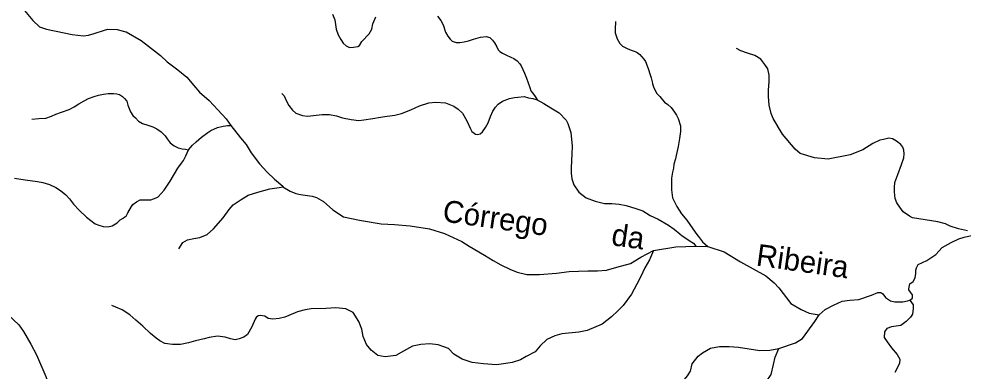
# Model space of a CAD drawing. Extents: x 436.3 to 500.4, y 8231 to 8286.4.
# Drawn here: x 484.1 to 492.75, y 8258.62 to 8261.84 of the extents above; entities that cross this region are included whole.
import ezdxf
from ezdxf.enums import TextEntityAlignment as Align

# ---------------------------------------------------------------- set-up
doc = ezdxf.new("R2010")
doc.units = 0
doc.header["$LTSCALE"] = 0.08
doc.linetypes.add('LONG_DASHED', pattern=[7.5, 6, -1.5])
doc.layers.add('61', color=7, linetype='Continuous')
doc.layers.add('9', color=7, linetype='LONG_DASHED', lineweight=25)

msp = doc.modelspace()

# ---------------------------------------------------------------- linework, layer by layer
at = {"layer": '9'}
msp.add_line((490.2994, 8259.7601), (490.4086, 8259.7547), dxfattribs=at)
for points in [[(484.1536, 8261.9144), (484.2296, 8261.8236), (484.2903, 8261.7668), (484.355, 8261.7442), (484.5186, 8261.7103), (484.5909, 8261.6953), (484.6936, 8261.684), (484.7394, 8261.6878), (484.7926, 8261.703), (484.8879, 8261.7334), (484.9184, 8261.7448), (485.0021, 8261.7411), (485.0707, 8261.7223), (485.0859, 8261.7185), (485.2229, 8261.6392), (485.2892, 8261.5876), (485.3995, 8261.5044), (485.4603, 8261.4439), (485.5592, 8261.3722), (485.6392, 8261.3041), (485.7039, 8261.2285), (485.757, 8261.168), (485.8446, 8261.0925), (485.9244, 8261.0054), (486.0006, 8260.9223), (486.0443, 8260.8634)], [(486.9745, 8261.8825), (486.9963, 8261.8298), (487.0085, 8261.743), (487.0241, 8261.6934), (487.0489, 8261.65), (487.0706, 8261.6159), (487.0987, 8261.5911), (487.1298, 8261.5756), (487.1671, 8261.5787), (487.2045, 8261.5848), (487.2202, 8261.5942), (487.2421, 8261.6314), (487.3076, 8261.7028), (487.3325, 8261.7431), (487.342, 8261.7927), (487.3702, 8261.8578)], [(487.9339, 8261.8623), (487.9642, 8261.823), (487.9858, 8261.7837), (488.0068, 8261.7158), (488.0296, 8261.679), (488.0499, 8261.6536), (488.0702, 8261.6346), (488.1057, 8261.6219), (488.1375, 8261.6219), (488.1782, 8261.6281), (488.2188, 8261.6383), (488.2646, 8261.6534), (488.3053, 8261.6647), (488.3294, 8261.6723), (488.3802, 8261.676), (488.4133, 8261.6684), (488.4386, 8261.6443), (488.4563, 8261.6202), (488.4766, 8261.5834), (488.4913, 8261.5547), (488.5053, 8261.5408), (488.5293, 8261.5243), (488.5674, 8261.5065), (488.6055, 8261.4886), (488.6334, 8261.4747), (488.6625, 8261.4544), (488.6892, 8261.4265), (488.7018, 8261.4087), (488.7309, 8261.3427), (488.7486, 8261.2946), (488.765, 8261.254), (488.7802, 8261.2109), (488.7903, 8261.1805), (488.8042, 8261.1602), (488.8296, 8261.1272), (488.8462, 8261.0973)], [(489.5625, 8261.8153), (489.5605, 8261.745), (489.5622, 8261.7112), (489.5685, 8261.6838), (489.5803, 8261.6564), (489.5903, 8261.6336), (489.6048, 8261.6117), (489.6294, 8261.5889), (489.6768, 8261.5633), (489.716, 8261.5495), (489.7424, 8261.5403), (489.7607, 8261.5302), (489.7852, 8261.5111), (489.8025, 8261.4936), (489.8246, 8261.4684), (489.8383, 8261.4474), (489.8528, 8261.4072), (489.8664, 8261.3735), (489.8791, 8261.3351), (489.8891, 8261.2995), (489.899, 8261.2622), (489.9037, 8261.2443), (489.9109, 8261.2178), (489.9227, 8261.1877), (489.9436, 8261.1549), (489.9682, 8261.1274), (489.9946, 8261.0973), (490.0138, 8261.0772), (490.0438, 8261.0552), (490.0739, 8261.0269), (490.1032, 8260.9861), (490.1222, 8260.9578), (490.1378, 8260.9277), (490.1592, 8260.8595), (490.1591, 8260.808), (490.1505, 8260.7437), (490.1375, 8260.6709), (490.1203, 8260.5896), (490.1135, 8260.5585), (490.098, 8260.5077), (490.0935, 8260.4722), (490.0868, 8260.4346), (490.0779, 8260.3814), (490.0756, 8260.3304), (490.0778, 8260.2728), (490.0866, 8260.2019), (490.1266, 8260.122), (490.1687, 8260.0532), (490.2156, 8259.9967), (490.2732, 8259.9167), (490.3087, 8259.8657), (490.3332, 8259.8347), (490.3597, 8259.7991), (490.4086, 8259.7547)], [(490.9571, 8261.3821), (490.9315, 8261.4193), (490.8938, 8261.4693), (490.8405, 8261.5017), (490.7715, 8261.5252), (490.7119, 8261.5458), (490.6711, 8261.5664)], [(492.7862, 8259.8999), (492.703, 8259.9175), (492.6259, 8259.9409), (492.5843, 8259.9644), (492.513, 8259.982), (492.2826, 8260.0192), (492.2541, 8260.0345), (492.1974, 8260.0729), (492.1665, 8260.1166), (492.1383, 8260.1551), (492.1228, 8260.1962), (492.1177, 8260.2553), (492.1177, 8260.2964), (492.1204, 8260.3401), (492.1489, 8260.4136), (492.1825, 8260.5062), (492.2033, 8260.5653), (492.206, 8260.6039), (492.2034, 8260.6374), (492.1932, 8260.6656), (492.1752, 8260.6887), (492.1366, 8260.7196), (492.098, 8260.7402), (492.067, 8260.7453), (492.0181, 8260.735), (491.9846, 8260.7273), (491.9196, 8260.6974), (491.8282, 8260.6389), (491.7108, 8260.5934), (491.5089, 8260.5546), (491.3852, 8260.5679), (491.2549, 8260.6071), (491.2095, 8260.6462), (491.0925, 8260.7831), (491.0083, 8260.9264), (490.9888, 8260.972), (490.9694, 8261.0501), (490.9631, 8261.1282), (490.9632, 8261.1868), (490.9699, 8261.2649), (490.97, 8261.3235), (490.9571, 8261.3821)], [(484.2208, 8260.9201), (484.2868, 8260.9269), (484.3483, 8260.9293), (484.403, 8260.9474), (484.4417, 8260.9656), (484.4918, 8260.9838), (484.5632, 8261.0088), (484.6088, 8261.0338), (484.6521, 8261.061), (484.7, 8261.0883), (484.741, 8261.1087), (484.7911, 8261.1268), (484.8322, 8261.1405), (484.8777, 8261.1496), (484.9187, 8261.1542), (484.9689, 8261.1543), (484.9985, 8261.152), (485.0236, 8261.1452), (485.0509, 8261.1271), (485.0691, 8261.1091), (485.0896, 8261.0842), (485.1009, 8261.048), (485.1123, 8261.0185), (485.1259, 8260.9868), (485.1464, 8260.9551), (485.1692, 8260.9326), (485.1988, 8260.9009), (485.2329, 8260.8805), (485.283, 8260.867), (485.3287, 8260.8512), (485.365, 8260.8309), (485.406, 8260.8038), (485.4413, 8260.7688), (485.4596, 8260.7399), (485.4891, 8260.7033), (485.5241, 8260.676), (485.5598, 8260.6581), (485.5962, 8260.649), (485.6281, 8260.6446), (485.6569, 8260.6412)], [(486.5094, 8261.1569), (486.5321, 8261.1344), (486.5485, 8261.0914), (486.5732, 8261.0442), (486.6082, 8261.0033), (486.639, 8260.9767), (486.6988, 8260.9542), (486.7461, 8260.948), (486.878, 8260.9624), (486.946, 8260.9624), (487.0098, 8260.9502), (487.0654, 8260.9337), (487.1457, 8260.9174), (487.2136, 8260.9071), (487.261, 8260.9133), (487.3434, 8260.9276), (487.4134, 8260.9378), (487.4751, 8260.948), (487.5431, 8260.9562), (487.6049, 8260.9726), (487.6904, 8261.0074), (487.7687, 8261.0422), (487.855, 8261.0688), (487.9188, 8261.0749), (488.0072, 8261.0686), (488.0854, 8261.0399), (488.1244, 8261.0132), (488.1634, 8260.9762), (488.2024, 8260.9044), (488.2352, 8260.8327), (488.2485, 8260.8074), (488.269, 8260.791), (488.2834, 8260.7827), (488.3019, 8260.7807), (488.3266, 8260.7868), (488.3451, 8260.8052), (488.3739, 8260.8441), (488.3987, 8260.8872), (488.4192, 8260.9444), (488.4399, 8260.9936), (488.4666, 8261.0305), (488.4892, 8261.0571), (488.5283, 8261.0859), (488.5941, 8261.1103), (488.6394, 8261.1184), (488.6702, 8261.1225), (488.7278, 8261.1265), (488.7688, 8261.1162), (488.8058, 8261.11), (488.8462, 8261.0973)], [(488.8462, 8261.0973), (488.9084, 8261.0646), (488.972, 8261.0236), (489.0479, 8260.9783), (489.1114, 8260.9105), (489.1279, 8260.8818), (489.1544, 8260.7977), (489.1666, 8260.6747), (489.1652, 8260.6018), (489.161, 8260.5424), (489.1589, 8260.4727), (489.1589, 8260.4276), (489.163, 8260.3744), (489.1835, 8260.319), (489.2286, 8260.2513), (489.2963, 8260.2), (489.3763, 8260.169), (489.4626, 8260.1504), (489.5302, 8260.1502), (489.598, 8260.1439), (489.6607, 8260.1301), (489.7509, 8260.1032), (489.8145, 8260.0805), (489.8801, 8260.0394), (489.954, 8260.0064), (490.0483, 8259.9509), (490.0995, 8259.9138), (490.1529, 8259.8707), (490.1755, 8259.8522), (490.2165, 8259.8255), (490.237, 8259.809), (490.2784, 8259.7862), (490.2994, 8259.7601)], [(485.6569, 8260.6412), (485.6918, 8260.6831), (485.726, 8260.7125), (485.7739, 8260.7556), (485.8309, 8260.7986), (485.8605, 8260.8168), (485.9198, 8260.844), (485.9734, 8260.856), (485.9953, 8260.8605), (486.0137, 8260.8627), (486.0443, 8260.8634)], [(486.0443, 8260.8634), (486.1299, 8260.7484), (486.1832, 8260.6879), (486.2301, 8260.6138), (486.3062, 8260.5117), (486.3747, 8260.4362), (486.4432, 8260.3719), (486.5194, 8260.3076), (486.5194, 8260.3)], [(484.0638, 8260.3802), (484.1606, 8260.3667), (484.2725, 8260.3505), (484.3216, 8260.341), (484.3817, 8260.3221), (484.4411, 8260.2952), (484.4844, 8260.2686), (484.5317, 8260.2297), (484.5668, 8260.1929), (484.6039, 8260.1418), (484.6555, 8260.0865), (484.7215, 8260.0232), (484.802, 8259.9639), (484.835, 8259.9496), (484.8742, 8259.9394), (484.9175, 8259.9354), (484.9566, 8259.9456), (485.0021, 8259.9723), (485.0288, 8259.999), (485.0577, 8260.0155), (485.0721, 8260.0257), (485.0845, 8260.0339), (485.101, 8260.0626), (485.133, 8260.1224), (485.1466, 8260.1405), (485.1785, 8260.1632), (485.2127, 8260.1814), (485.2538, 8260.1815), (485.3107, 8260.1837), (485.3586, 8260.1996), (485.3791, 8260.211), (485.4338, 8260.2699), (485.4863, 8260.3538), (485.5592, 8260.4716), (485.5913, 8260.5177), (485.6085, 8260.5412), (485.6303, 8260.5836), (485.6569, 8260.6412)], [(485.5681, 8259.7337), (485.605, 8259.7913), (485.6471, 8259.8175), (485.7051, 8259.8281), (485.7577, 8259.8385), (485.8262, 8259.8648), (485.8841, 8259.9171), (485.9736, 8260.0166), (486.0263, 8260.0951), (486.0632, 8260.137), (486.1368, 8260.1842), (486.2001, 8260.2261), (486.2896, 8260.2524), (486.4002, 8260.2838), (486.4844, 8260.2943), (486.5194, 8260.3)], [(486.5194, 8260.3), (486.5863, 8260.2624), (486.6389, 8260.2415), (486.681, 8260.231), (486.7863, 8260.2154), (486.8284, 8260.2049), (486.8915, 8260.1682), (486.9757, 8260.0898), (487.0757, 8260.0271), (487.2203, 8259.9979), (487.4187, 8259.9639), (487.5417, 8259.957), (487.6852, 8259.9433), (487.8628, 8259.9159), (487.9995, 8259.875), (488.1566, 8259.8), (488.2249, 8259.7591), (488.3635, 8259.6762), (488.4453, 8259.6288), (488.5136, 8259.5879), (488.5954, 8259.5469), (488.6637, 8259.5196), (488.7524, 8259.499), (488.8684, 8259.4988), (489.0252, 8259.512), (489.1411, 8259.5254), (489.3115, 8259.5317), (489.4002, 8259.5315), (489.4819, 8259.5381), (489.5773, 8259.565), (489.6999, 8259.5987), (489.7943, 8259.6567), (489.911, 8259.7205)], [(492.2579, 8259.2642), (492.283, 8259.2842), (492.283, 8259.3142), (492.2628, 8259.3392), (492.2477, 8259.3592), (492.2477, 8259.3691), (492.2578, 8259.4141), (492.2879, 8259.4342), (492.3079, 8259.4693), (492.313, 8259.5092), (492.313, 8259.5393), (492.318, 8259.5593), (492.3339, 8259.5911), (492.4143, 8259.6261), (492.4948, 8259.6813), (492.5552, 8259.7464), (492.6358, 8259.7916), (492.7063, 8259.8269), (492.7566, 8259.8419), (492.8221, 8259.8571), (492.8624, 8259.8773), (492.8753, 8259.8884)], [(489.911, 8259.7205), (489.875, 8259.635), (489.8335, 8259.5612), (489.795, 8259.4815), (489.7595, 8259.4105), (489.709, 8259.3203), (489.635, 8259.217), (489.5846, 8259.1669), (489.5283, 8259.1109), (489.4415, 8259.0454), (489.3051, 8258.9867), (489.2281, 8258.9721), (489.0739, 8258.9577), (489.0086, 8258.9371), (488.9345, 8258.9048), (488.8753, 8258.8458), (488.8279, 8258.7927), (488.7449, 8258.7485), (488.6945, 8258.719), (488.6174, 8258.6955), (488.56, 8258.6838), (488.474, 8258.6722), (488.3551, 8258.6813), (488.2506, 8258.6935), (488.1614, 8258.7261), (488.0841, 8258.7705), (488.0365, 8258.8209), (487.9919, 8258.8387), (487.9413, 8258.8564), (487.864, 8258.8654), (487.7809, 8258.8596), (487.7066, 8258.8448), (487.6234, 8258.7976), (487.5521, 8258.7592), (487.457, 8258.7474), (487.3874, 8258.7574), (487.3278, 8258.8067), (487.2856, 8258.8585), (487.2557, 8258.9324), (487.2407, 8258.999), (487.2133, 8259.0704), (487.1612, 8259.1517), (487.0966, 8259.1863), (487.0029, 8259.1937), (486.9121, 8259.1871), (486.7792, 8259.1838), (486.7246, 8259.1764), (486.6527, 8259.1566), (486.5733, 8259.1245), (486.5361, 8259.1097), (486.4865, 8259.0973), (486.4282, 8259.0899), (486.3835, 8259.0973), (486.3537, 8259.1195), (486.3114, 8259.1243), (486.2941, 8259.1218), (486.2743, 8259.1071), (486.2644, 8259.0898), (486.2347, 8259.0207), (486.1952, 8258.9517), (486.1629, 8258.927), (486.1207, 8258.9097), (486.0811, 8258.9023), (486.0388, 8258.9096), (485.9916, 8258.9268), (485.9221, 8258.9366), (485.8452, 8258.9243), (485.798, 8258.9119), (485.7186, 8258.892), (485.6566, 8258.8747), (485.5821, 8258.8599), (485.5101, 8258.8598), (485.4381, 8258.8696), (485.3933, 8258.8916), (485.3586, 8258.9163), (485.3088, 8258.9606), (485.2366, 8259.027), (485.1744, 8259.0812), (485.1198, 8259.1304)], [(489.911, 8259.7205), (490.1154, 8259.7539), (490.2994, 8259.7601)], [(490.4086, 8259.7547), (490.5571, 8259.7055), (490.7081, 8259.6162), (490.9398, 8259.4865), (491.0172, 8259.4239), (491.0582, 8259.3763), (491.1673, 8259.2334), (491.2629, 8259.179), (491.3379, 8259.1449), (491.4265, 8259.1311)], [(481.9907, 8259.6476), (482.0749, 8259.5359), (482.1958, 8259.4436), (482.3057, 8259.4173), (482.4206, 8259.4226), (482.576, 8259.4332), (482.728, 8259.4578), (482.8587, 8259.4684), (482.9719, 8259.4473), (483.1771, 8259.405), (483.354, 8259.3628), (483.6512, 8259.3031), (483.7893, 8259.2609), (483.8886, 8259.2118), (484.0056, 8259.1308), (484.1034, 8259.0383), (484.1461, 8258.9784), (484.2137, 8258.8624), (484.2635, 8258.7639), (484.349, 8258.5669), (484.3882, 8258.4578), (484.4632, 8258.2467), (484.531, 8258.0902), (484.5562, 8258.0303)], [(491.4265, 8259.1311), (491.4843, 8259.1795), (491.5595, 8259.2194), (491.6399, 8259.2543), (491.7101, 8259.2642), (491.7905, 8259.2692), (491.906, 8259.3091), (491.9662, 8259.3341), (491.9913, 8259.3341), (492.0114, 8259.324), (492.0367, 8259.2891), (492.0819, 8259.2591), (492.1221, 8259.2491), (492.1925, 8259.2491), (492.2378, 8259.2592), (492.2579, 8259.2642)], [(492.2579, 8259.2642), (492.2891, 8259.2225), (492.2891, 8259.187), (492.2813, 8259.1357), (492.2654, 8259.108), (492.2258, 8259.0686), (492.1742, 8259.033), (492.091, 8259.0212), (492.0474, 8259.0054), (492.0275, 8258.9739), (492.0237, 8258.9226), (492.0515, 8258.8831), (492.0913, 8258.828), (492.143, 8258.7688), (492.1668, 8258.7254), (492.1629, 8258.686), (492.1194, 8258.6031)], [(485.1198, 8259.1304), (485.0479, 8259.1751), (484.9915, 8259.2015), (484.9539, 8259.2162)], [(491.0602, 8258.822), (491.2117, 8258.8744), (491.2768, 8258.9142), (491.387, 8259.069), (491.4265, 8259.1311)], [(489.8053, 8258.3089), (489.8484, 8258.3426), (489.9336, 8258.3874), (490.0338, 8258.4371), (490.114, 8258.4719), (490.1791, 8258.5217), (490.2241, 8258.5716), (490.2492, 8258.6165), (490.2641, 8258.6815), (490.3192, 8258.7514), (490.3592, 8258.7813), (490.4344, 8258.8261), (490.5145, 8258.8409), (490.6048, 8258.8407), (490.6901, 8258.8355), (490.8857, 8258.8051), (490.9758, 8258.8084), (491.0602, 8258.822)], [(490.4661, 8258.0568), (490.4932, 8258.1656), (490.5281, 8258.2394), (490.5592, 8258.2899), (490.6253, 8258.3402), (490.711, 8258.3867), (490.7968, 8258.4215), (490.8201, 8258.437), (490.9331, 8258.5067), (490.9759, 8258.5649), (490.9876, 8258.5844), (491.0114, 8258.6752), (491.0238, 8258.743), (491.0602, 8258.822)]]:
    msp.add_lwpolyline(points, dxfattribs=at)

# ---------------------------------------------------------------- texts
at = {"layer": '61'}
msp.add_text('Córrego        da              Ribeira        ', height=0.2, rotation=351.988, dxfattribs=at).set_placement((490.1222, 8259.684), align=Align.CENTER)

doc.saveas('drawing.dxf')
